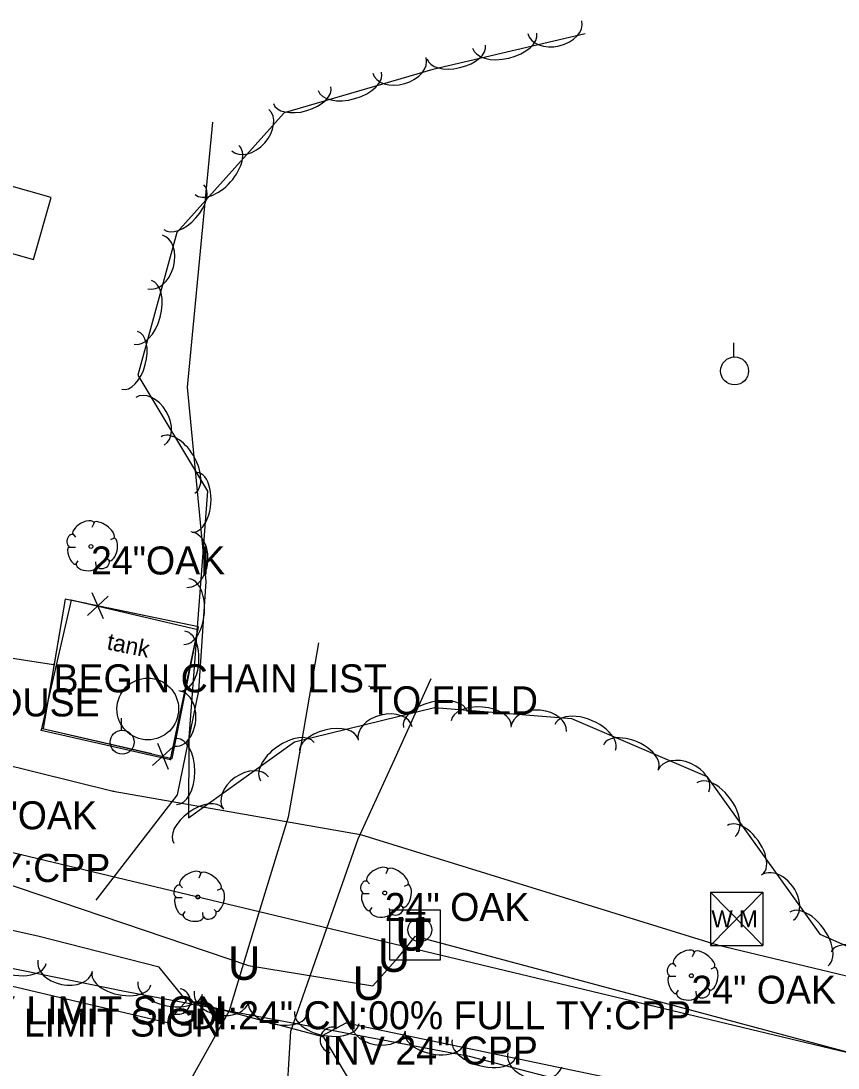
# Model space of a CAD drawing. Extents: x 1441650 to 1491889, y 345904 to 358319.
# Drawn here: x 1447211.5 to 1447357.2, y 354233 to 354419.8 of the extents above; entities that cross this region are included whole.
import ezdxf

# ---------------------------------------------------------------- set-up
doc = ezdxf.new("R2010")
doc.units = 0
for name, color, linetype in [('Default', 7, 'Continuous'), ('S_BUILDING', 7, 'Continuous'), ('S_CROSS_DRAIN', 7, 'Continuous'), ('S_CROSS_DRAIN_ANNOT', 7, 'Continuous'), ('S_DITCHLINE', 7, 'Continuous'), ('S_DRG_PT_SYM', 7, 'Continuous'), ('S_FENCE', 7, 'Continuous'), ('S_GAS_UTILITIES', 7, 'Continuous'), ('S_GRAVEL_ROAD', 7, 'Continuous'), ('S_MISC_STRUCTURES', 7, 'Continuous'), ('S_MISC_STRUCTURES_ANNOT', 7, 'Continuous'), ('S_MSC_PT_SYM', 7, 'Continuous'), ('S_SANITARY_SEWER', 7, 'Continuous'), ('S_SANITARY_SEWER_ANNOT', 7, 'Continuous'), ('S_SIGN_ANNOT', 7, 'Continuous'), ('S_STREAM', 7, 'Continuous'), ('S_SURVEY_TEXT_ANNOT', 7, 'Continuous'), ('S_TELEPHONE_UTILITIES', 7, 'Continuous'), ('S_TREE', 7, 'Continuous'), ('S_TREE_ANNOT', 7, 'Continuous'), ('S_UNDERGROUND_CABLE', 7, 'Continuous'), ('S_UTILITY_POLE', 7, 'Continuous'), ('S_UTL_PT_SYM', 7, 'Continuous'), ('S_WATER_UTILITIES', 7, 'Continuous')]:
    doc.layers.add(name, color=color, linetype=linetype)

msp = doc.modelspace()

# ---------------------------------------------------------------- linework, layer by layer
at = {"layer": 'S_BUILDING'}
msp.add_lwpolyline([(1447173.85, 354388.56), (1447213.74, 354377.24), (1447216.87, 354388.28), (1447176.98, 354399.6)], close=True, dxfattribs=at)
at = {"layer": 'S_CROSS_DRAIN'}
msp.add_line((1447241.67, 354244.93), (1447265.24, 354238.64), dxfattribs=at)
for centre, start, end in [((1447239.41, 354244.9), 257.9379, 78.2671), ((1447267.12, 354238.02), 75.6189, 255.9481)]:
    msp.add_arc(centre, 2.3, start, end, dxfattribs=at)
at = {"layer": 'S_DITCHLINE'}
msp.add_lwpolyline([(1447161.96, 354264.89), (1447166.74, 354257.76), (1447187.2, 354252.95), (1447207.67, 354248.14), (1447222.61, 354244.63), (1447237.56, 354241.11), (1447241.03, 354245), (1447236.15, 354250.98), (1447214.51, 354256.52), (1447190.54, 354261.84), (1447166.58, 354267.15)], close=True, dxfattribs=at)
for points in [[(1447265.28, 354238.8), (1447269.5, 354241.06), (1447292.83, 354236.2), (1447316.15, 354231.34), (1447339.47, 354226.48), (1447362.79, 354221.62), (1447385.96, 354215.71), (1447409.12, 354209.8), (1447432.29, 354203.88), (1447455.46, 354197.97), (1447474.09, 354193.79), (1447492.73, 354189.6), (1447511.37, 354185.42), (1447530.01, 354181.23), (1447538.26, 354175.02)], [(1447265.28, 354238.8), (1447269.65, 354231.43), (1447292.15, 354226.12), (1447314.65, 354220.81), (1447337.15, 354215.5), (1447359.65, 354210.2), (1447383.59, 354204.44), (1447407.53, 354198.69), (1447431.47, 354192.94), (1447455.42, 354187.19), (1447474.48, 354183.24), (1447493.54, 354179.29), (1447512.59, 354175.33), (1447531.65, 354171.38), (1447538.26, 354175.02)]]:
    msp.add_lwpolyline(points, dxfattribs=at)
at = {"layer": 'S_DRG_PT_SYM'}
for points in [[(1447241.67, 354244.93), (1447241.67, 354244.98), (1447241.67, 354244.93), (1447241.61, 354244.93), (1447241.67, 354244.93), (1447241.67, 354244.88), (1447241.67, 354244.93), (1447241.72, 354244.93)], [(1447265.24, 354238.64), (1447265.24, 354238.69), (1447265.24, 354238.64), (1447265.19, 354238.64), (1447265.24, 354238.64), (1447265.24, 354238.59), (1447265.24, 354238.64), (1447265.29, 354238.64)]]:
    msp.add_lwpolyline(points, dxfattribs=at)
at = {"layer": 'S_FENCE'}
for p, q in [((1447226.19, 354313.16), (1447224.21, 354317.75)), ((1447220.44, 354316.47), (1447215.11, 354293.3)), ((1447243.05, 354311.15), (1447220.44, 354316.47)), ((1447227.02, 354317.17), (1447223.38, 354313.74)), ((1447238.18, 354288.06), (1447243.05, 354311.15)), ((1447215.11, 354293.3), (1447238.18, 354288.06)), ((1447234.93, 354286.96), (1447238.64, 354290.31)), ((1447235.85, 354290.96), (1447237.72, 354286.32))]:
    msp.add_line(p, q, dxfattribs=at)
for points in [[(1447215.35, 354293.58), (1447238.46, 354288.25), (1447243.15, 354311.74), (1447219.39, 354316.66), (1447215.45, 354293.55)], [(1447223.24, 354315.86), (1447219.39, 354316.66), (1447216.69, 354300.83)], [(1447242.43, 354308.14), (1447243.15, 354311.74), (1447227.16, 354315.05)], [(1447238.52, 354288.52), (1447242.43, 354308.14)], [(1447216.69, 354300.83), (1447215.45, 354293.55)], [(1447215.35, 354293.58), (1447234.84, 354289.09)]]:
    msp.add_lwpolyline(points, dxfattribs=at)
at = {"layer": 'S_GAS_UTILITIES'}
msp.add_line((1446885.45, 354349.24), (1447571.1, 354184.98), dxfattribs=at)
at = {"layer": 'S_GRAVEL_ROAD'}
for points in [[(1447264.57, 354308.85), (1447261.85, 354293.31), (1447259.12, 354277.78), (1447253.86, 354260.51), (1447248.6, 354243.24), (1447241.63, 354230.7), (1447231.4, 354221.27)], [(1447266.64, 354212.53), (1447258.73, 354224.84), (1447259.59, 354239.62), (1447265.6, 354256.75), (1447271.61, 354273.88), (1447278.13, 354288.18), (1447284.65, 354302.48)]]:
    msp.add_lwpolyline(points, dxfattribs=at)
at = {"layer": 'S_MISC_STRUCTURES'}
msp.add_ellipse((1447234.11, 354297.06), major_axis=(-1.11, -5.39), ratio=0.999412, dxfattribs=at)
at = {"layer": 'S_MSC_PT_SYM'}
for points in [[(1447220.44, 354316.47), (1447220.44, 354316.52), (1447220.44, 354316.47), (1447220.39, 354316.47), (1447220.44, 354316.47), (1447220.44, 354316.42), (1447220.44, 354316.47), (1447220.49, 354316.47)], [(1447243.05, 354311.15), (1447243.05, 354311.2), (1447243.05, 354311.15), (1447243, 354311.15), (1447243.05, 354311.15), (1447243.05, 354311.1), (1447243.05, 354311.15), (1447243.1, 354311.15)], [(1447273.59, 354301.1), (1447273.59, 354301.15), (1447273.59, 354301.1), (1447273.54, 354301.1), (1447273.59, 354301.1), (1447273.59, 354301.05), (1447273.59, 354301.1), (1447273.64, 354301.1)], [(1447215.11, 354293.3), (1447215.11, 354293.35), (1447215.11, 354293.3), (1447215.06, 354293.3), (1447215.11, 354293.3), (1447215.11, 354293.25), (1447215.11, 354293.3), (1447215.16, 354293.3)], [(1447238.18, 354288.06), (1447238.18, 354288.11), (1447238.18, 354288.06), (1447238.13, 354288.06), (1447238.18, 354288.06), (1447238.18, 354288.01), (1447238.18, 354288.06), (1447238.23, 354288.06)]]:
    msp.add_lwpolyline(points, dxfattribs=at)
at = {"layer": 'S_SANITARY_SEWER'}
msp.add_line((1447103.16, 354322.03), (1447217.3, 354305.02), dxfattribs=at)
at = {"layer": 'S_STREAM'}
msp.add_lwpolyline([(1447245.66, 354401.71), (1447241.14, 354354.46), (1447244.45, 354319.82), (1447243.16, 354300.31), (1447239.33, 354281.77), (1447224.86, 354262.98)], dxfattribs=at)
at = {"layer": 'S_TELEPHONE_UTILITIES'}
msp.add_lwpolyline([(1447277.27, 354252.23), (1447277.27, 354261.23), (1447286.27, 354261.23), (1447286.27, 354252.23)], close=True, dxfattribs=at)
at = {"layer": 'S_TREE'}
for p, q in [((1447224.54, 354330.29), (1447224.15, 354329.44)), ((1447220.74, 354328.28), (1447221.25, 354327.7)), ((1447228.1, 354327.5), (1447227.45, 354327.23)), ((1447220.08, 354325.95), (1447221.21, 354325.95)), ((1447221.25, 354322.78), (1447221.71, 354323.47)), ((1447224.93, 354322.51), (1447224.85, 354323.28)), ((1447227.33, 354323.4), (1447226.86, 354323.82)), ((1447243.59, 354267.76), (1447243.2, 354266.91)), ((1447276.92, 354268.49), (1447276.53, 354267.63)), ((1447239.79, 354265.75), (1447240.3, 354265.17)), ((1447247.16, 354264.97), (1447246.5, 354264.7)), ((1447273.12, 354266.47), (1447273.63, 354265.89)), ((1447280.49, 354265.7), (1447279.83, 354265.42)), ((1447239.13, 354263.42), (1447240.26, 354263.42)), ((1447272.46, 354264.15), (1447273.59, 354264.15)), ((1447246.38, 354260.86), (1447245.92, 354261.29)), ((1447273.63, 354260.97), (1447274.09, 354261.67)), ((1447277.31, 354260.7), (1447277.23, 354261.47)), ((1447279.71, 354261.59), (1447279.25, 354262.01)), ((1447240.3, 354260.24), (1447240.76, 354260.94)), ((1447243.98, 354259.97), (1447243.9, 354260.75)), ((1447331.59, 354253.72), (1447331.2, 354252.87)), ((1447327.79, 354251.71), (1447328.29, 354251.13)), ((1447335.15, 354250.93), (1447334.49, 354250.66)), ((1447327.13, 354249.38), (1447328.25, 354249.38)), ((1447328.29, 354246.2), (1447328.76, 354246.9)), ((1447331.97, 354245.93), (1447331.9, 354246.71)), ((1447334.38, 354246.82), (1447333.91, 354247.25))]:
    msp.add_line(p, q, dxfattribs=at)
for points in [[(1447312.07, 354417.47), (1447284.92, 354411.11), (1447258.41, 354403.42), (1447239.31, 354382.03), (1447232.35, 354356.59), (1447244.77, 354335.93), (1447241.42, 354291.95), (1447241.38, 354277.64), (1447260.29, 354291.18), (1447285.26, 354297.3), (1447309.67, 354295.36), (1447333.77, 354285.03), (1447353.96, 354256.91), (1447379.9, 354245.47)], [(1447554.08, 354354.01), (1447539.72, 354339.24), (1447517.03, 354329.25), (1447512.18, 354312.75), (1447525.65, 354293.75), (1447544.98, 354289.69), (1447561.15, 354278.87), (1447535.56, 354271.63), (1447514.59, 354266.45), (1447514.49, 354237.08), (1447509.92, 354214.08), (1447505.26, 354191.06), (1447488.43, 354184.2), (1447418.78, 354200.58), (1447350.99, 354219.59), (1447291.45, 354235.06), (1447229.94, 354246.67), (1447181.83, 354256.49), (1447170.79, 354260.87)]]:
    msp.add_lwpolyline(points, dxfattribs=at)
for centre in [(1447223.98, 354326.05), (1447243.03, 354263.52), (1447276.36, 354264.24), (1447331.03, 354249.48)]:
    msp.add_circle(centre, 0.341, dxfattribs=at)
for centre, major_axis, ratio, start_param, end_param in [((1447306.7, 354418.65), (4.82, 1.13), 0.685184, 3.141593, 6.283185), ((1447297.74, 354416.29), (5.71, 1.34), 0.549978, 3.141593, 6.283185), ((1447289.11, 354414.27), (5.21, 1.22), 0.540599, 3.141593, 6.283185), ((1447278.97, 354411.86), (4.76, 1.38), 0.685194, 3.141593, 6.283185), ((1447270.15, 354409.03), (5.64, 1.63), 0.549986, 3.141593, 6.283185), ((1447261.64, 354406.56), (5.13, 1.49), 0.540607, 3.141593, 6.283185), ((1447252.42, 354400.29), (3.3, 3.7), 0.685291, 3.141593, 6.283185), ((1447246.45, 354393.21), (3.91, 4.38), 0.550064, 3.141593, 6.283185), ((1447240.54, 354386.59), (3.56, 3.99), 0.540684, 3.141593, 6.283185), ((1447235.41, 354376.79), (1.31, 4.78), 0.685307, 3.141593, 6.283185), ((1447233.22, 354367.8), (1.55, 5.66), 0.550077, 3.141593, 6.283185), ((1447230.88, 354359.24), (1.41, 5.16), 0.540696, 3.141593, 6.283185), ((1447234.5, 354348.39), (-2.55, 4.25), 0.685183, 3.141593, 6.283185), ((1447239.49, 354340.59), (-3.02, 5.03), 0.549977, 3.141593, 6.283185), ((1447242.49, 354333.94), (0.41, 5.33), 0.540683, 3.141587, 6.28318), ((1447222.64, 354329.25), (1.86, 1.08), 0.471018, 0, 3.141593), ((1447226.3, 354328.93), (-1.81, 1.36), 0.405113, 3.141593, 6.283186), ((1447241.44, 354323.69), (0.38, 4.94), 0.685291, 3.141584, 6.283177), ((1447220.41, 354327.14), (0.31, 1.03), 0.646762, 0, 3.141593), ((1447227.65, 354325.52), (0.46, 2.04), 0.482994, 3.141593, 6.283185), ((1447220.72, 354324.49), (-0.61, 1.6), 0.420543, 6.283185, 9.424777), ((1447223.18, 354322.71), (-1.83, 0.19), 0.529943, 0, 3.141593), ((1447226.13, 354323), (1.09, 0.46), 0.711534, 3.141592, 6.283185), ((1447241, 354314.44), (0.45, 5.85), 0.550064, 3.141587, 6.28318), ((1447240.33, 354305.59), (0.41, 5.33), 0.540683, 3.141587, 6.28318), ((1447239.29, 354295.34), (0.38, 4.94), 0.685291, 3.141584, 6.283177), ((1447285.39, 354295.15), (-5.7, -1.4), 0.54998, 3.141593, 6.283185), ((1447293.55, 354294.52), (-5.33, 0.42), 0.540561, 3.141593, 6.283185), ((1447303.8, 354293.44), (-4.94, 0.39), 0.685136, 3.141593, 6.283185), ((1447276.46, 354292.69), (-4.81, -1.18), 0.685186, 3.141593, 6.283185), ((1447312.1, 354292.01), (-5.39, 2.31), 0.549924, 3.141559, 6.283152), ((1447266.39, 354290.49), (-5.19, -1.27), 0.540601, 3.141593, 6.283185), ((1447239.28, 354285.92), (0.02, 5.87), 0.550056, 3.141593, 6.283185), ((1447259, 354287.65), (-4.77, -3.42), 0.550038, 3.141593, 6.283185), ((1447320.25, 354288.52), (-4.91, 2.11), 0.540546, 3.14156, 6.283153), ((1447329.62, 354284.22), (-4.55, 1.95), 0.685117, 3.141538, 6.28313), ((1447251.62, 354282.05), (-4.03, -2.88), 0.685258, 3.141593, 6.283185), ((1447335.4, 354279.11), (-3.42, 4.77), 0.550038, 3.141331, 6.282924), ((1447243.1, 354276.26), (-4.35, -3.11), 0.540658, 3.141593, 6.283185), ((1447340.57, 354271.91), (-3.12, 4.34), 0.540658, 3.141339, 6.282932), ((1447275.03, 354267.44), (1.86, 1.08), 0.471018, 0, 3.141593), ((1447278.68, 354267.12), (-1.81, 1.36), 0.405113, 3.141593, 6.283186), ((1447241.7, 354266.72), (1.86, 1.08), 0.471018, 0, 3.141593), ((1447245.35, 354266.4), (-1.81, 1.36), 0.405113, 3.141593, 6.283186), ((1447346.37, 354263.39), (-2.89, 4.02), 0.685258, 3.141164, 6.282757), ((1447239.46, 354264.6), (0.31, 1.03), 0.646762, 0, 3.141593), ((1447246.71, 354262.99), (0.46, 2.04), 0.482994, 3.141593, 6.283185), ((1447272.79, 354265.33), (0.31, 1.03), 0.646762, 0, 3.141593), ((1447280.04, 354263.71), (0.46, 2.04), 0.482994, 3.141593, 6.283185), ((1447239.77, 354261.95), (-0.61, 1.6), 0.420543, 6.283185, 9.424777), ((1447273.1, 354262.68), (-0.61, 1.6), 0.420543, 6.283185, 9.424777), ((1447278.52, 354261.19), (1.09, 0.46), 0.711534, 3.141592, 6.283185), ((1447351.98, 354256.02), (-3.42, 4.77), 0.550038, 3.141331, 6.282924), ((1447242.23, 354260.17), (-1.83, 0.19), 0.529943, 0, 3.141593), ((1447245.19, 354260.47), (1.09, 0.46), 0.711534, 3.141592, 6.283185), ((1447275.56, 354260.9), (-1.83, 0.19), 0.529943, 0, 3.141593), ((1447210.27, 354252.85), (5.75, -1.17), 0.550084, 3.141593, 6.283186), ((1447329.69, 354252.68), (1.86, 1.08), 0.471018, 0, 3.141593), ((1447333.35, 354252.36), (-1.81, 1.36), 0.405113, 3.141593, 6.283186), ((1447360.82, 354251.57), (-4.89, 2.16), 0.540608, 3.141316, 6.282909), ((1447219.39, 354251.26), (4.86, -0.99), 0.685316, 3.141594, 6.283186), ((1447229.43, 354248.94), (5.24, -1.07), 0.540704, 3.141593, 6.283186), ((1447327.46, 354250.56), (0.31, 1.03), 0.646762, 0, 3.141593), ((1447334.7, 354248.95), (0.46, 2.04), 0.482994, 3.141593, 6.283185), ((1447238.11, 354247.29), (5.77, -1.09), 0.550141, 3.141595, 6.283188), ((1447327.76, 354247.91), (-0.61, 1.6), 0.420543, 6.283185, 9.424777), ((1447247.26, 354245.83), (4.87, -0.92), 0.685388, 3.141597, 6.283189), ((1447330.22, 354246.13), (-1.83, 0.19), 0.529943, 0, 3.141593), ((1447333.18, 354246.43), (1.09, 0.46), 0.711534, 3.141592, 6.283185), ((1447257.33, 354243.66), (5.25, -0.99), 0.54076, 3.141595, 6.283188), ((1447266.04, 354242.02), (5.77, -1.09), 0.550141, 3.141595, 6.283188), ((1447275.19, 354240.56), (4.87, -0.92), 0.685388, 3.141597, 6.283189), ((1447285.26, 354238.39), (5.25, -0.99), 0.54076, 3.141595, 6.283188), ((1447294.08, 354236.57), (5.68, -1.48), 0.550081, 3.141593, 6.283186), ((1447303.11, 354234.5), (4.8, -1.25), 0.685312, 3.141593, 6.283186)]:
    msp.add_ellipse(centre, major_axis=major_axis, ratio=ratio, start_param=start_param, end_param=end_param, dxfattribs=at)
at = {"layer": 'S_UNDERGROUND_CABLE'}
for p, q in [((1447170.52, 354278.89), (1447252.04, 354251.28)), ((1447278.74, 354252.71), (1447281.86, 354256.51)), ((1447281.86, 354256.51), (1447570.01, 354179.21)), ((1447274.26, 354247.7), (1447278.74, 354252.71)), ((1447252.04, 354251.28), (1447274.26, 354247.7))]:
    msp.add_line(p, q, dxfattribs=at)
at = {"layer": 'S_UTILITY_POLE'}
for p, q in [((1447338.59, 354359.87), (1447338.59, 354362.35)), ((1447229.41, 354293.29), (1447229.41, 354295.4)), ((1447282.49, 354259.81), (1447282.49, 354261.92))]:
    msp.add_line(p, q, dxfattribs=at)
for centre, radius in [((1447338.74, 354357.36), 2.5), ((1447229.53, 354291.15), 2.13), ((1447282.61, 354257.67), 2.13)]:
    msp.add_circle(centre, radius, dxfattribs=at)
at = {"layer": 'S_UTL_PT_SYM'}
for points in [[(1447217.3, 354305.02), (1447217.3, 354305.07), (1447217.3, 354305.02), (1447217.25, 354305.02), (1447217.3, 354305.02), (1447217.3, 354304.97), (1447217.3, 354305.02), (1447217.35, 354305.02)], [(1447227.93, 354282.41), (1447227.93, 354282.46), (1447227.93, 354282.41), (1447227.88, 354282.41), (1447227.93, 354282.41), (1447227.93, 354282.36), (1447227.93, 354282.41), (1447227.98, 354282.41)], [(1447272.04, 354274.65), (1447272.04, 354274.7), (1447272.04, 354274.65), (1447271.99, 354274.65), (1447272.04, 354274.65), (1447272.04, 354274.6), (1447272.04, 354274.65), (1447272.09, 354274.65)], [(1447335.62, 354254.99), (1447335.62, 354255.04), (1447335.62, 354254.99), (1447335.57, 354254.99), (1447335.62, 354254.99), (1447335.62, 354254.94), (1447335.62, 354254.99), (1447335.67, 354254.99)]]:
    msp.add_lwpolyline(points, dxfattribs=at)
at = {"layer": 'S_WATER_UTILITIES'}
for p, q in [((1447189.13, 354292.01), (1447227.93, 354282.41)), ((1447227.93, 354282.41), (1447272.04, 354274.65)), ((1447272.04, 354274.65), (1447335.62, 354254.99)), ((1447334.42, 354264.36), (1447343.75, 354264.36)), ((1447334.42, 354264.36), (1447334.42, 354254.86)), ((1447334.42, 354264.36), (1447343.75, 354254.86)), ((1447343.75, 354264.36), (1447334.42, 354254.86)), ((1447343.75, 354264.36), (1447343.75, 354254.86)), ((1447334.42, 354254.86), (1447343.75, 354254.86)), ((1447335.62, 354254.99), (1447442.81, 354229.26))]:
    msp.add_line(p, q, dxfattribs=at)

# ---------------------------------------------------------------- texts
at = {"layer": 'Default'}
for p in [(1447278.23, 354253.96), (1447275.11, 354250.17), (1447248.41, 354248.74), (1447270.63, 354245.15)]:
    msp.add_text('U', height=6, rotation=360, dxfattribs=at).set_placement(p)
at = {"layer": 'S_CROSS_DRAIN_ANNOT'}
for s, p in [('DI:24" CN:00% FULL TY:CPP', (1447138.1, 354266.19)), ('DI:24" CN:00% FULL TY:CPP', (1447241.67, 354239.93)), ('INV 24" CPP', (1447265.24, 354233.64))]:
    msp.add_text(s, height=5, dxfattribs=at).set_placement(p)
at = {"layer": 'S_MISC_STRUCTURES_ANNOT'}
msp.add_text('tank', height=3, rotation=348.3134, dxfattribs=at).set_placement((1447226.66, 354307.73))
at = {"layer": 'S_SANITARY_SEWER_ANNOT'}
msp.add_text('BEGIN CHAIN LIST', height=5, dxfattribs=at).set_placement((1447217.3, 354300.02))
at = {"layer": 'S_SIGN_ANNOT'}
for p in [(1447195.37, 354240.81), (1447194.91, 354238.63)]:
    msp.add_text('CITY LIMIT SIGN', height=5, dxfattribs=at).set_placement(p)
at = {"layer": 'S_SURVEY_TEXT_ANNOT'}
for s, p in [('TO TRAILER HOUSE', (1447160.51, 354295.73)), ('TO FIELD', (1447273.59, 354296.1))]:
    msp.add_text(s, height=5, dxfattribs=at).set_placement(p)
at = {"layer": 'S_TELEPHONE_UTILITIES'}
msp.add_text('T', height=6, rotation=360, dxfattribs=at).set_placement((1447279.84, 354253.73))
at = {"layer": 'S_TREE_ANNOT'}
for s, p in [('24"OAK', (1447223.98, 354321.05)), ('24"OAK', (1447201.12, 354275.6)), ('24" OAK', (1447276.36, 354259.24)), ('24" OAK', (1447331.03, 354244.48))]:
    msp.add_text(s, height=5, dxfattribs=at).set_placement(p)
at = {"layer": 'S_WATER_UTILITIES'}
msp.add_text('W M', height=3, rotation=360, dxfattribs=at).set_placement((1447334.62, 354258.12))

doc.saveas('drawing.dxf')
